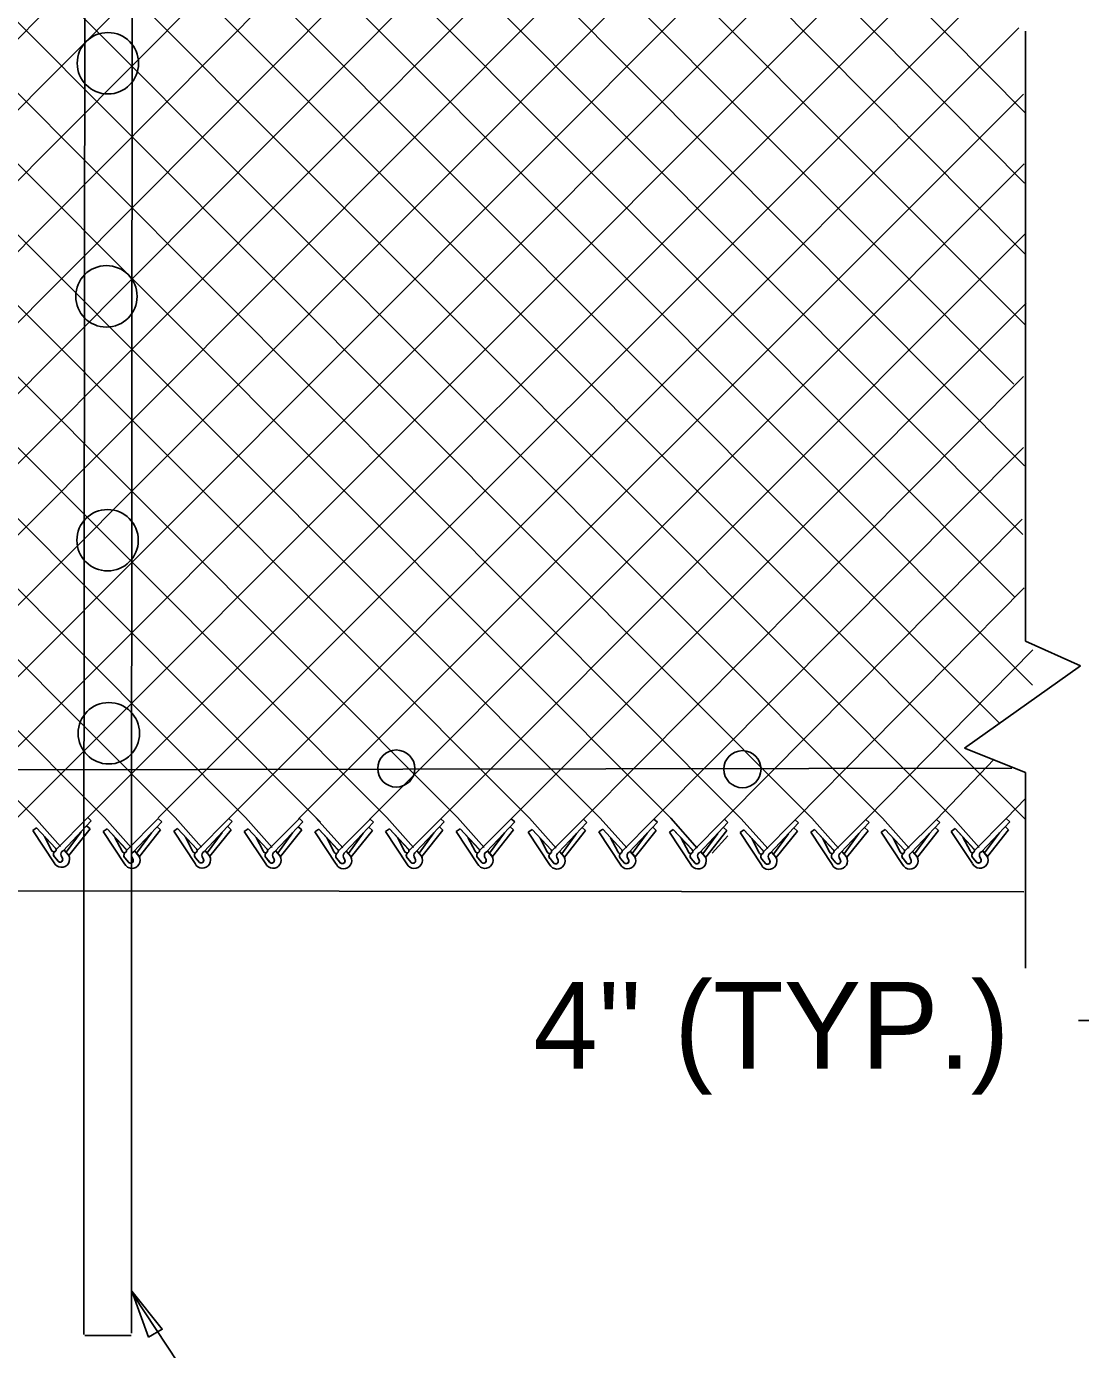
# Model space of a CAD drawing. Extents: x 0 to 1270, y 0 to 830.
# Drawn here: x 348.9 to 409, y 573.4 to 648.9 of the extents above; entities that cross this region are included whole.
import ezdxf

# ---------------------------------------------------------------- set-up
doc = ezdxf.new("R2010")
doc.units = 0
for name, color, linetype in [('CT_Dimensions', 7, 'Continuous'), ('sb_Chainlink Fence', 7, 'Continuous'), ('sb_Earth', 7, 'Continuous'), ('sb_Existing Structural Steel', 7, 'Continuous')]:
    doc.layers.add(name, color=color, linetype=linetype)

msp = doc.modelspace()

# ---------------------------------------------------------------- linework, layer by layer
at = {"layer": 'CT_Dimensions'}
for p, q in [((408.897, 592.207), (411.411, 592.207)), ((354.982, 576.53), (363.476, 563.709))]:
    msp.add_line(p, q, dxfattribs=at)
msp.add_lwpolyline([(355.835, 574.139), (354.885, 576.758), (356.633, 574.589)], close=True, dxfattribs=at)
at = {"layer": 'sb_Chainlink Fence'}
for p, q in [((295.969, 657.227), (349.311, 603.835)), ((300, 657.257), (353.33, 603.776)), ((304.029, 657.234), (357.357, 603.786)), ((304.062, 603.674), (357.353, 657.203)), ((308.055, 657.231), (361.384, 603.778)), ((308.089, 603.684), (361.38, 657.192)), ((312.077, 657.249), (365.65, 603.512)), ((312.116, 603.676), (365.407, 657.201)), ((316.105, 657.227), (369.444, 603.771)), ((316.147, 603.646), (369.438, 657.23)), ((320.132, 657.224), (373.47, 603.773)), ((320.175, 603.669), (373.466, 657.208)), ((324.178, 657.226), (377.583, 603.738)), ((324.202, 603.671), (377.493, 657.205)), ((328.191, 603.719), (381.586, 657.218)), ((328.205, 657.215), (381.61, 603.748)), ((332.218, 603.73), (385.615, 657.196)), ((332.232, 657.224), (385.637, 603.739)), ((336.245, 603.721), (389.641, 657.193)), ((336.263, 657.253), (389.668, 603.71)), ((340.277, 603.692), (393.688, 657.194)), ((340.291, 657.231), (393.697, 603.732)), ((344.318, 657.228), (397.723, 603.735)), ((344.328, 603.746), (397.714, 657.184)), ((348.324, 657.29), (401.713, 603.783)), ((348.357, 603.768), (401.741, 657.192)), ((352.352, 657.267), (405.856, 603.674)), ((352.383, 603.771), (405.713, 657.09)), ((356.379, 657.265), (404.44, 609.12)), ((360.425, 657.266), (406.272, 611.318)), ((364.452, 657.256), (405.298, 616.323)), ((368.479, 657.264), (405.722, 619.93)), ((372.51, 657.294), (405.833, 623.849)), ((376.538, 657.272), (405.209, 628.504)), ((380.565, 657.269), (405.901, 631.842)), ((384.658, 657.282), (405.862, 635.912)), ((388.687, 657.259), (405.83, 639.974)), ((392.713, 657.256), (405.839, 643.996)), ((356.403, 603.75), (406.873, 654.22)), ((360.429, 603.723), (405.505, 648.822)), ((405.883, 648.627), (405.883, 613.83)), ((364.411, 603.697), (405.759, 645.045)), ((368.461, 603.673), (405.81, 641.066)), ((372.516, 603.707), (405.84, 637.065)), ((376.542, 603.71), (405.918, 633.112)), ((380.655, 603.674), (405.767, 628.931)), ((384.682, 603.684), (405.76, 624.893)), ((388.709, 603.676), (405.696, 620.799)), ((392.74, 603.646), (405.808, 616.88)), ((405.883, 613.83), (409.015, 612.438)), ((396.769, 603.669), (406.301, 613.343)), ((409.015, 612.438), (402.404, 607.74)), ((402.404, 607.74), (405.883, 606.349)), ((400.795, 603.671), (404.087, 607.098)), ((405.883, 606.349), (405.883, 595.174)), ((404.785, 603.719), (405.901, 604.882)), ((349.311, 603.835), (350.829, 602.126)), ((349.239, 603.041), (349.462, 603.193)), ((349.462, 603.193), (350.54, 602.031)), ((349.462, 603.193), (350.547, 602.024)), ((350.57, 601.95), (352.383, 603.771)), ((350.968, 601.878), (352.581, 603.592)), ((352.514, 603.129), (351.308, 601.611)), ((352.514, 603.129), (352.316, 603.308)), ((352.581, 603.592), (352.383, 603.771)), ((353.258, 602.982), (353.481, 603.135)), ((353.33, 603.776), (354.848, 602.067)), ((353.481, 603.135), (354.559, 601.973)), ((353.481, 603.135), (354.566, 601.966)), ((354.588, 601.891), (356.402, 603.713)), ((354.987, 601.82), (356.6, 603.533)), ((356.533, 603.07), (355.326, 601.553)), ((356.533, 603.07), (356.335, 603.25)), ((356.6, 603.533), (356.402, 603.713)), ((357.285, 602.993), (357.508, 603.145)), ((357.357, 603.786), (358.875, 602.078)), ((357.508, 603.145), (358.586, 601.983)), ((357.508, 603.145), (358.593, 601.976)), ((358.615, 601.901), (360.429, 603.723)), ((359.014, 601.83), (360.627, 603.544)), ((360.56, 603.081), (359.353, 601.563)), ((360.56, 603.081), (360.362, 603.26)), ((360.627, 603.544), (360.429, 603.723)), ((361.312, 602.984), (361.535, 603.137)), ((361.384, 603.778), (362.902, 602.069)), ((361.535, 603.137), (362.613, 601.975)), ((361.535, 603.137), (362.62, 601.968)), ((362.642, 601.893), (364.456, 603.715)), ((363.041, 601.822), (364.654, 603.535)), ((364.587, 603.072), (363.38, 601.555)), ((364.587, 603.072), (364.389, 603.252)), ((364.654, 603.535), (364.456, 603.715)), ((365.343, 602.954), (365.566, 603.107)), ((365.415, 603.748), (366.933, 602.039)), ((365.566, 603.107), (366.644, 601.945)), ((365.566, 603.107), (366.651, 601.938)), ((366.674, 601.863), (368.487, 603.685)), ((367.072, 601.792), (368.685, 603.505)), ((368.618, 603.042), (368.42, 603.222)), ((368.685, 603.505), (368.487, 603.685)), ((369.372, 602.977), (369.595, 603.129)), ((369.444, 603.771), (370.961, 602.062)), ((369.595, 603.129), (370.673, 601.967)), ((369.595, 603.129), (370.679, 601.961)), ((370.702, 601.886), (372.516, 603.707)), ((371.101, 601.814), (372.713, 603.528)), ((372.646, 603.065), (372.448, 603.244)), ((372.713, 603.528), (372.516, 603.707)), ((373.398, 602.98), (373.621, 603.132)), ((373.47, 603.773), (374.988, 602.065)), ((373.621, 603.132), (374.699, 601.97)), ((373.621, 603.132), (374.706, 601.963)), ((374.728, 601.889), (376.542, 603.71)), ((375.127, 601.817), (376.74, 603.531)), ((376.673, 603.068), (375.466, 601.55)), ((376.673, 603.068), (376.475, 603.247)), ((376.74, 603.531), (376.542, 603.71)), ((377.511, 602.944), (377.734, 603.096)), ((377.583, 603.738), (379.101, 602.029)), ((377.734, 603.096), (378.812, 601.934)), ((377.734, 603.096), (378.819, 601.927)), ((378.842, 601.853), (380.655, 603.674)), ((379.241, 601.781), (380.853, 603.495)), ((380.786, 603.032), (380.588, 603.211)), ((380.853, 603.495), (380.655, 603.674)), ((381.538, 602.954), (381.761, 603.106)), ((381.61, 603.748), (383.128, 602.039)), ((381.761, 603.106), (382.839, 601.945)), ((381.761, 603.106), (382.846, 601.938)), ((382.868, 601.863), (384.682, 603.684)), ((383.267, 601.792), (384.88, 603.505)), ((384.813, 603.042), (384.615, 603.221)), ((384.88, 603.505), (384.682, 603.684)), ((385.565, 602.946), (385.788, 603.098)), ((385.637, 603.739), (387.155, 602.031)), ((385.788, 603.098), (386.866, 601.936)), ((385.788, 603.098), (386.873, 601.929)), ((386.896, 601.855), (388.709, 603.676)), ((387.294, 601.783), (388.907, 603.497)), ((388.84, 603.034), (388.642, 603.213)), ((388.907, 603.497), (388.709, 603.676)), ((389.596, 602.916), (389.819, 603.068)), ((389.668, 603.71), (391.186, 602.001)), ((389.819, 603.068), (390.897, 601.906)), ((389.819, 603.068), (390.904, 601.9)), ((390.927, 601.825), (392.74, 603.646)), ((391.326, 601.754), (392.938, 603.467)), ((392.871, 603.004), (392.673, 603.183)), ((392.938, 603.467), (392.74, 603.646)), ((393.625, 602.938), (393.848, 603.091)), ((393.697, 603.732), (395.214, 602.023)), ((393.848, 603.091), (394.926, 601.929)), ((393.848, 603.091), (394.933, 601.922)), ((394.955, 601.847), (396.769, 603.669)), ((395.354, 601.776), (396.967, 603.489)), ((396.9, 603.026), (396.702, 603.206)), ((396.967, 603.489), (396.769, 603.669)), ((397.651, 602.941), (397.874, 603.093)), ((397.723, 603.735), (399.241, 602.026)), ((397.874, 603.093), (398.952, 601.932)), ((397.874, 603.093), (398.959, 601.925)), ((398.982, 601.85), (400.795, 603.671)), ((399.38, 601.779), (400.993, 603.492)), ((400.926, 603.029), (400.728, 603.208)), ((400.993, 603.492), (400.795, 603.671)), ((401.641, 602.989), (401.864, 603.142)), ((401.713, 603.783), (403.231, 602.074)), ((401.864, 603.142), (402.942, 601.98)), ((401.864, 603.142), (402.949, 601.973)), ((402.971, 601.898), (404.785, 603.719)), ((403.37, 601.827), (404.983, 603.54)), ((404.916, 603.077), (403.709, 601.56)), ((404.916, 603.077), (404.718, 603.256)), ((404.983, 603.54), (404.785, 603.719)), ((350.457, 601.196), (349.239, 603.041)), ((350.319, 601.924), (349.913, 602.7)), ((351.994, 602.963), (351.146, 601.808)), ((354.476, 601.138), (353.258, 602.982)), ((354.338, 601.866), (353.932, 602.641)), ((356.013, 602.904), (355.165, 601.749)), ((358.503, 601.148), (357.285, 602.993)), ((358.364, 601.876), (357.959, 602.652)), ((360.04, 602.914), (359.192, 601.76)), ((362.53, 601.14), (361.312, 602.984)), ((362.392, 601.868), (361.986, 602.643)), ((364.067, 602.906), (363.219, 601.751)), ((366.561, 601.11), (365.343, 602.954)), ((366.423, 601.838), (366.017, 602.614)), ((368.098, 602.876), (367.25, 601.721)), ((368.618, 603.042), (367.412, 601.525)), ((370.59, 601.132), (369.372, 602.977)), ((370.451, 601.86), (370.045, 602.636)), ((372.127, 602.899), (371.278, 601.744)), ((372.646, 603.065), (371.44, 601.547)), ((374.616, 601.135), (373.398, 602.98)), ((374.478, 601.863), (374.072, 602.639)), ((376.153, 602.902), (375.305, 601.747)), ((378.73, 601.099), (377.511, 602.944)), ((378.591, 601.827), (378.185, 602.603)), ((380.267, 602.866), (379.418, 601.711)), ((380.786, 603.032), (379.58, 601.514)), ((382.756, 601.11), (381.538, 602.954)), ((382.618, 601.837), (382.212, 602.613)), ((384.293, 602.876), (383.445, 601.721)), ((384.813, 603.042), (383.606, 601.525)), ((386.783, 601.101), (385.565, 602.946)), ((386.645, 601.829), (386.239, 602.605)), ((388.32, 602.868), (387.472, 601.713)), ((388.84, 603.034), (387.634, 601.516)), ((388.889, 602.724), (388.011, 601.735)), ((390.815, 601.071), (389.596, 602.916)), ((390.676, 601.799), (390.27, 602.575)), ((392.352, 602.838), (391.503, 601.683)), ((392.871, 603.004), (391.665, 601.487)), ((394.843, 601.094), (393.625, 602.938)), ((394.704, 601.822), (394.299, 602.597)), ((396.38, 602.86), (395.532, 601.705)), ((396.9, 603.026), (395.693, 601.509)), ((398.869, 601.097), (397.651, 602.941)), ((398.731, 601.824), (398.325, 602.6)), ((400.406, 602.863), (399.558, 601.708)), ((400.926, 603.029), (399.72, 601.512)), ((402.859, 601.145), (401.641, 602.989)), ((402.72, 601.872), (402.315, 602.648)), ((404.396, 602.911), (403.548, 601.756)), ((350.944, 601.432), (350.863, 601.609)), ((350.863, 601.602), (350.944, 601.436)), ((351.036, 601.926), (351.284, 601.633)), ((351.039, 601.922), (351.285, 601.632)), ((351.284, 601.633), (351.302, 601.599)), ((351.302, 601.599), (351.317, 601.563)), ((355.055, 601.868), (355.302, 601.575)), ((355.058, 601.863), (355.304, 601.574)), ((355.302, 601.575), (355.321, 601.541)), ((358.99, 601.383), (358.908, 601.561)), ((359.082, 601.878), (359.329, 601.585)), ((359.085, 601.874), (359.33, 601.584)), ((359.329, 601.585), (359.347, 601.551)), ((363.109, 601.87), (363.356, 601.577)), ((363.112, 601.865), (363.358, 601.576)), ((363.356, 601.577), (363.375, 601.543)), ((367.14, 601.84), (367.388, 601.547)), ((367.143, 601.835), (367.389, 601.546)), ((371.168, 601.862), (371.416, 601.569)), ((371.172, 601.858), (371.417, 601.568)), ((371.416, 601.569), (371.434, 601.535)), ((375.195, 601.865), (375.442, 601.572)), ((375.198, 601.861), (375.444, 601.571)), ((375.442, 601.572), (375.461, 601.538)), ((379.308, 601.829), (379.556, 601.536)), ((379.311, 601.825), (379.557, 601.535)), ((383.335, 601.839), (383.582, 601.546)), ((383.338, 601.835), (383.584, 601.545)), ((387.362, 601.831), (387.61, 601.538)), ((387.365, 601.827), (387.611, 601.537)), ((391.393, 601.801), (391.641, 601.508)), ((391.396, 601.797), (391.642, 601.507)), ((395.422, 601.824), (395.669, 601.531)), ((395.425, 601.819), (395.67, 601.53)), ((399.448, 601.827), (399.696, 601.533)), ((399.451, 601.822), (399.697, 601.532)), ((403.438, 601.875), (403.685, 601.581)), ((403.441, 601.87), (403.687, 601.58)), ((403.685, 601.581), (403.704, 601.547)), ((350.683, 601.289), (350.481, 601.531)), ((350.481, 601.531), (350.704, 601.267)), ((354.702, 601.23), (354.5, 601.472)), ((354.5, 601.472), (354.723, 601.209)), ((354.963, 601.373), (354.881, 601.55)), ((354.882, 601.544), (354.963, 601.377)), ((355.321, 601.541), (355.336, 601.504)), ((358.729, 601.241), (358.527, 601.482)), ((358.527, 601.482), (358.749, 601.219)), ((358.908, 601.554), (358.99, 601.387)), ((359.347, 601.551), (359.363, 601.514)), ((362.756, 601.232), (362.554, 601.474)), ((362.554, 601.474), (362.777, 601.211)), ((363.017, 601.375), (362.935, 601.552)), ((362.936, 601.546), (363.017, 601.379)), ((363.375, 601.543), (363.39, 601.506)), ((366.787, 601.203), (366.585, 601.444)), ((366.585, 601.444), (366.808, 601.181)), ((367.048, 601.345), (366.966, 601.522)), ((366.967, 601.516), (367.048, 601.349)), ((367.388, 601.547), (367.406, 601.513)), ((367.406, 601.513), (367.421, 601.476)), ((370.816, 601.225), (370.614, 601.467)), ((370.614, 601.467), (370.836, 601.203)), ((371.077, 601.368), (370.995, 601.545)), ((370.995, 601.539), (371.076, 601.372)), ((371.434, 601.535), (371.45, 601.499)), ((374.842, 601.228), (374.64, 601.47)), ((374.64, 601.47), (374.863, 601.206)), ((375.103, 601.371), (375.021, 601.548)), ((375.022, 601.541), (375.103, 601.375)), ((375.461, 601.538), (375.476, 601.502)), ((378.955, 601.192), (378.753, 601.434)), ((378.753, 601.434), (378.976, 601.17)), ((379.216, 601.335), (379.135, 601.512)), ((379.135, 601.505), (379.216, 601.339)), ((379.556, 601.536), (379.574, 601.502)), ((379.574, 601.502), (379.589, 601.466)), ((382.982, 601.202), (382.78, 601.444)), ((382.78, 601.444), (383.003, 601.18)), ((383.243, 601.345), (383.161, 601.522)), ((383.162, 601.516), (383.243, 601.349)), ((383.582, 601.546), (383.601, 601.512)), ((383.601, 601.512), (383.616, 601.476)), ((387.009, 601.194), (386.807, 601.436)), ((386.807, 601.436), (387.03, 601.172)), ((387.27, 601.336), (387.189, 601.514)), ((387.189, 601.507), (387.27, 601.341)), ((387.61, 601.538), (387.628, 601.504)), ((387.628, 601.504), (387.643, 601.468)), ((391.04, 601.164), (390.838, 601.406)), ((390.838, 601.406), (391.061, 601.142)), ((391.302, 601.307), (391.22, 601.484)), ((391.22, 601.478), (391.301, 601.311)), ((391.641, 601.508), (391.659, 601.474)), ((391.659, 601.474), (391.675, 601.438)), ((395.069, 601.186), (394.867, 601.428)), ((394.867, 601.428), (395.089, 601.165)), ((395.33, 601.329), (395.248, 601.506)), ((395.248, 601.5), (395.33, 601.333)), ((395.669, 601.531), (395.687, 601.497)), ((395.687, 601.497), (395.703, 601.46)), ((399.095, 601.189), (398.893, 601.431)), ((398.893, 601.431), (399.116, 601.168)), ((399.356, 601.332), (399.275, 601.509)), ((399.275, 601.503), (399.356, 601.336)), ((399.696, 601.533), (399.714, 601.499)), ((399.714, 601.499), (399.729, 601.463)), ((403.085, 601.237), (402.883, 601.479)), ((402.883, 601.479), (403.106, 601.216)), ((403.346, 601.38), (403.264, 601.557)), ((403.265, 601.551), (403.346, 601.384)), ((403.704, 601.547), (403.719, 601.511))]:
    msp.add_line(p, q, dxfattribs=at)
for centre, radius, start, end in [((350.445, 601.946), 0.128, 189.93044, 40.97854), ((350.611, 601.672), 0.192, 126.99475, 219.79834), ((350.616, 601.672), 0.195, 127.76564, 226.33281), ((350.877, 601.404), 0.468, 206.32022, 29.22687), ((351.056, 601.688), 0.209, 114.84217, 203.51672), ((354.464, 601.888), 0.128, 189.93044, 40.97854), ((354.63, 601.614), 0.192, 126.99475, 219.79834), ((354.635, 601.614), 0.195, 127.76564, 226.33281), ((354.896, 601.345), 0.468, 206.32022, 29.22687), ((355.075, 601.63), 0.209, 114.84217, 203.51672), ((358.49, 601.898), 0.128, 189.93044, 40.97854), ((358.657, 601.624), 0.192, 126.99475, 219.79834), ((358.662, 601.624), 0.195, 127.76564, 226.33281), ((358.922, 601.355), 0.468, 206.32022, 29.22687), ((359.102, 601.64), 0.209, 114.84217, 203.51672), ((362.517, 601.89), 0.128, 189.93044, 40.97854), ((362.684, 601.616), 0.192, 126.99475, 219.79834), ((362.689, 601.616), 0.195, 127.76564, 226.33281), ((362.949, 601.347), 0.468, 206.32022, 29.22687), ((363.129, 601.632), 0.209, 114.84217, 203.51672), ((366.549, 601.86), 0.128, 189.93044, 40.97854), ((366.715, 601.586), 0.192, 126.99475, 219.79834), ((366.72, 601.586), 0.195, 127.76564, 226.33281), ((367.16, 601.602), 0.209, 114.84217, 203.51672), ((370.577, 601.882), 0.128, 189.93044, 40.97854), ((370.743, 601.608), 0.192, 126.99475, 219.79834), ((370.749, 601.608), 0.195, 127.76564, 226.33281), ((371.009, 601.34), 0.468, 206.32022, 29.22687), ((371.189, 601.624), 0.209, 114.84217, 203.51672), ((374.603, 601.885), 0.128, 189.93044, 40.97854), ((374.77, 601.611), 0.192, 126.99475, 219.79834), ((374.775, 601.611), 0.195, 127.76564, 226.33281), ((375.035, 601.343), 0.468, 206.32022, 29.22687), ((375.215, 601.627), 0.209, 114.84217, 203.51672), ((378.717, 601.849), 0.128, 189.93044, 40.97854), ((378.883, 601.575), 0.192, 126.99475, 219.79834), ((378.888, 601.575), 0.195, 127.76564, 226.33281), ((379.329, 601.591), 0.209, 114.84217, 203.51672), ((382.744, 601.859), 0.128, 189.93044, 40.97854), ((382.91, 601.586), 0.192, 126.99475, 219.79834), ((382.915, 601.585), 0.195, 127.76564, 226.33281), ((383.355, 601.602), 0.209, 114.84217, 203.51672), ((386.771, 601.851), 0.128, 189.93044, 40.97854), ((386.937, 601.577), 0.192, 126.99475, 219.79834), ((386.942, 601.577), 0.195, 127.76564, 226.33281), ((387.382, 601.593), 0.209, 114.84217, 203.51672), ((390.802, 601.821), 0.128, 189.93044, 40.97854), ((390.968, 601.547), 0.192, 126.99475, 219.79834), ((390.973, 601.547), 0.195, 127.76564, 226.33281), ((391.414, 601.564), 0.209, 114.84217, 203.51672), ((394.83, 601.844), 0.128, 189.93044, 40.97854), ((394.997, 601.57), 0.192, 126.99475, 219.79834), ((395.002, 601.57), 0.195, 127.76564, 226.33281), ((395.442, 601.586), 0.209, 114.84217, 203.51672), ((398.857, 601.846), 0.128, 189.93044, 40.97854), ((399.023, 601.573), 0.192, 126.99475, 219.79834), ((399.028, 601.572), 0.195, 127.76564, 226.33281), ((399.468, 601.589), 0.209, 114.84217, 203.51672), ((402.846, 601.895), 0.128, 189.93044, 40.97854), ((403.013, 601.621), 0.192, 126.99475, 219.79834), ((403.018, 601.621), 0.195, 127.76564, 226.33281), ((403.278, 601.352), 0.468, 206.32022, 29.22687), ((403.458, 601.637), 0.209, 114.84217, 203.51672), ((350.8, 601.386), 0.152, 219.86319, 17.48524), ((350.8, 601.385), 0.152, 230.7826, 19.26564), ((354.819, 601.328), 0.152, 219.86319, 17.48524), ((354.819, 601.327), 0.152, 230.7826, 19.26564), ((358.845, 601.338), 0.152, 219.86319, 17.48524), ((358.846, 601.337), 0.152, 230.7826, 19.26564), ((362.872, 601.329), 0.152, 219.86319, 17.48524), ((362.873, 601.329), 0.152, 230.7826, 19.26564), ((366.981, 601.317), 0.468, 206.32022, 29.22687), ((366.904, 601.3), 0.152, 219.86319, 17.48524), ((366.904, 601.299), 0.152, 230.7826, 19.26564), ((370.932, 601.322), 0.152, 219.86319, 17.48524), ((370.933, 601.321), 0.152, 230.7826, 19.26564), ((374.958, 601.325), 0.152, 219.86319, 17.48524), ((374.959, 601.324), 0.152, 230.7826, 19.26564), ((379.149, 601.307), 0.468, 206.32022, 29.22687), ((379.072, 601.289), 0.152, 219.86319, 17.48524), ((379.072, 601.288), 0.152, 230.7826, 19.26564), ((383.176, 601.317), 0.468, 206.32022, 29.22687), ((383.099, 601.299), 0.152, 219.86319, 17.48524), ((383.099, 601.299), 0.152, 230.7826, 19.26564), ((387.203, 601.309), 0.468, 206.32022, 29.22687), ((387.126, 601.291), 0.152, 219.86319, 17.48524), ((387.126, 601.29), 0.152, 230.7826, 19.26564), ((391.234, 601.279), 0.468, 206.32022, 29.22687), ((391.157, 601.261), 0.152, 219.86319, 17.48524), ((391.157, 601.26), 0.152, 230.7826, 19.26564), ((395.262, 601.301), 0.468, 206.32022, 29.22687), ((395.185, 601.284), 0.152, 219.86319, 17.48524), ((395.186, 601.283), 0.152, 230.7826, 19.26564), ((399.289, 601.304), 0.468, 206.32022, 29.22687), ((399.212, 601.286), 0.152, 219.86319, 17.48524), ((399.212, 601.286), 0.152, 230.7826, 19.26564), ((403.201, 601.334), 0.152, 219.86319, 17.48524), ((403.202, 601.334), 0.152, 230.7826, 19.26564)]:
    msp.add_arc(centre, radius, start, end, dxfattribs=at)
at = {"layer": 'sb_Earth'}
msp.add_line((278.787, 599.642), (405.79, 599.541), dxfattribs=at)
at = {"layer": 'sb_Existing Structural Steel'}
for p, q in [((352.162, 599.642), (352.214, 660.813)), ((354.876, 599.699), (354.928, 660.812)), ((65.549, 606.032), (405.109, 606.595)), ((352.162, 574.28), (352.162, 599.642)), ((354.876, 574.356), (354.876, 599.699)), ((352.213, 574.235), (354.857, 574.235))]:
    msp.add_line(p, q, dxfattribs=at)
for centre, radius in [((353.528, 646.805), 1.752), ((353.444, 633.509), 1.752), ((353.512, 619.595), 1.752), ((353.581, 608.583), 1.752), ((369.98, 606.571), 1.06), ((389.732, 606.533), 1.06)]:
    msp.add_circle(centre, radius, dxfattribs=at)

# ---------------------------------------------------------------- texts
at = {"layer": 'CT_Dimensions'}
msp.add_text("4'' (TYP.)", height=4.95, rotation=360, dxfattribs=at).set_placement((377.795, 589.45))

doc.saveas('drawing.dxf')
